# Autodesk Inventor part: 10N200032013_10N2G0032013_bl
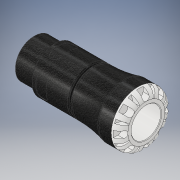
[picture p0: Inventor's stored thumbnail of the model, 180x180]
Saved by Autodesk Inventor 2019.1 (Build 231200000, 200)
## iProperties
Created: 2016-12
Part Number: 10N200032013_10N2G0032013_bl
Material: PVC-Piping
Description: PLASSON MALE ADAPTOR 32X1.1/4" SERIES 1
Document SubType Name: Modeling
Designer: KIM
Mass: 61.7504 g
Surface Area: 140.097 cm^2
Volume: 44.1074 cm^3
Density: 1.4 g/cm^3
Appearance: Black Cast
Author: KIM
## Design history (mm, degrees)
derived "10N20.ipt"
feature "Solid1::10N20.ipt" dims "ScaleForDerivedMember" = 10
tag "TaggingFeature1"
body "Solid1"
other parameters: "d0" = 122 [user parameter], "d1" = 23.1 [user parameter], "d2" = 32 [user parameter], "d4" = 58 [user parameter], "d6" = 55 [user parameter], "d8" = 49.3 [user parameter], "d13" = 7.2 [user parameter], "d14" = 7.2 [user parameter], "d15" = 0 [user parameter], "d17" = 360 deg [user parameter], "d19" = 8 deg [user parameter], "d20" = 0.64 [user parameter], "d21" = 0.64 [user parameter], "d22" = 8 deg [user parameter], "d24" = 0 [user parameter], "d26" = 360 deg [user parameter], "d32" = 0.925 [user parameter], "d33" = 5.8 [user parameter], "d34" = 41.91 [user parameter], "d35" = 4 [user parameter], "d38" = 22 [user parameter], "d39" = 1.2573 [user parameter], "d42" = 11.2 [user parameter], "d43" = 7.36 [user parameter], "d45" = 14.112 [user parameter], "d46" = 0 [user parameter], "d59" = 360 deg [user parameter], "d61" = 9.52 [user parameter], "d62" = 0.64 [user parameter], "d64" = 0 [user parameter], "d65" = 0.58 [user parameter], "d69" = 2 [user parameter], "d70" = 1.83 [user parameter], "d71" = 3 [user parameter], "d73" = 1 [user parameter], "d_" = 32 [user parameter], "E_" = 58 [user parameter], "H_" = 122 [user parameter], "l_" = 55 [user parameter], "R_" = 41.91 [user parameter], "l_2" = 22 [user parameter], "d9" = 9 [user parameter], "d11" = 58 [user parameter]
